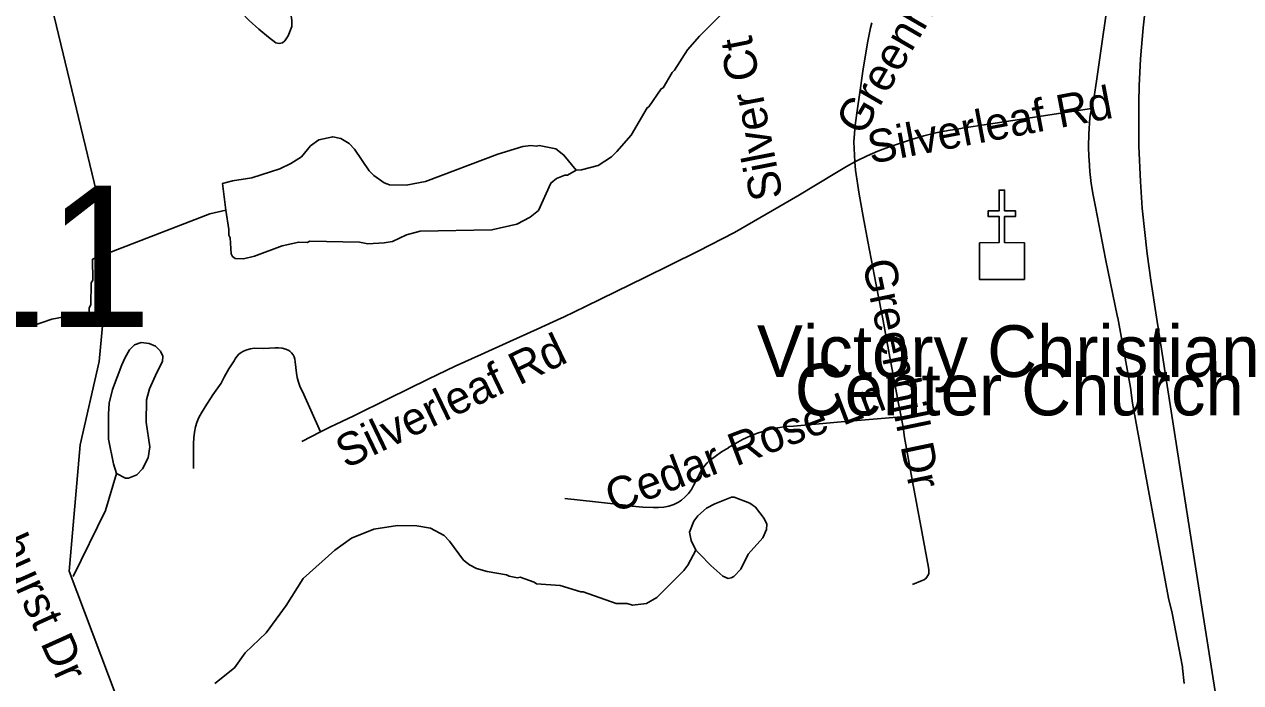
# Model space of a CAD drawing. Extents: x 1383679 to 1536984, y 460658 to 651027.
# Drawn here: x 1435276 to 1438807, y 512005 to 513915 of the extents above; entities that cross this region are included whole.
import ezdxf

# ---------------------------------------------------------------- set-up
doc = ezdxf.new("R2010")
doc.units = 0
for name, color, linetype in [('Exist Cultural Church CELL', 7, 'Continuous'), ('Exist Cultural Church Label', 7, 'Continuous'), ('Exist Hydrographic Creek Single Shore', 7, 'Continuous'), ('Exist Hydrographic Misc Water Feature', 7, 'Continuous'), ('Exist Railroad Mainline', 7, 'Continuous'), ('Exist Road Non-System Type 51', 7, 'Continuous'), ('Exist Road Non-System Type 51 Label', 7, 'Continuous'), ('Exist Road Primary Interstate Structure Ovrhead Sign Number Label', 7, 'Continuous')]:
    doc.layers.add(name, color=color, linetype=linetype)

msp = doc.modelspace()

# ---------------------------------------------------------------- linework, layer by layer
at = {"layer": 'Exist Cultural Church CELL'}
msp.add_lwpolyline([(1438048.9, 513281.7), (1438105.9, 513281.9), (1438105.9, 513358), (1438073.9, 513358), (1438073.9, 513374), (1438105.9, 513374), (1438105.9, 513434.1), (1438121.9, 513434.1), (1438121.9, 513374), (1438153.9, 513374), (1438153.9, 513358), (1438121.9, 513358), (1438121.9, 513281.9), (1438179.5, 513281.7), (1438179.5, 513175.3), (1438048.9, 513175.3)], close=True, dxfattribs=at)
at = {"layer": 'Exist Hydrographic Creek Single Shore'}
msp.add_lwpolyline([(1436493.4, 509139), (1436445.4, 509248.2), (1436458.4, 509458.1), (1436137.4, 510130.8), (1435971.4, 510574), (1435913.4, 510601.5), (1435772.4, 511037.6), (1435792.4, 511227.6), (1435852.4, 511301.8), (1435846.4, 511426.7), (1435659.5, 511647.1), (1435629.4, 511825), (1435564.4, 511908.3), (1435405.4, 512328.4), (1435437.4, 512695.4), (1435492.5, 512937.2), (1435523.4, 513268), (1435362.5, 513937.6), (1435309.4, 514240.7), (1435323.4, 514539.1), (1435285.5, 514707.3), (1435189.5, 514925.8)], dxfattribs=at)
at = {"layer": 'Exist Hydrographic Misc Water Feature'}
for points in [[(1436877.7, 513492.5), (1436893.2, 513492.7), (1436941.5, 513505.6), (1436980.1, 513530.7), (1436996.4, 513546.3), (1437037.5, 513593.4), (1437084.4, 513673.1), (1437089.3, 513676.2), (1437124.9, 513728.5), (1437130.5, 513731.2), (1437156.3, 513775.5), (1437163.6, 513782.5), (1437200.9, 513841.6), (1437235.8, 513880.8), (1437299.1, 513943.4)], [(1435861.1, 513375.9), (1435850.8, 513453), (1435880.4, 513461.5), (1435936.6, 513470.2), (1436017.2, 513496.4), (1436049.5, 513511.7), (1436079.9, 513531), (1436106.6, 513562.3), (1436131, 513579.8), (1436171.2, 513588.9), (1436195, 513584.4), (1436218.7, 513569.8), (1436234.4, 513553.5), (1436277.1, 513490.6), (1436290.8, 513476.3), (1436320.3, 513455.6), (1436336.2, 513449.2), (1436384.2, 513448.2), (1436440.4, 513458.9), (1436650.2, 513538.1), (1436722.6, 513560.5), (1436746.7, 513564), (1436762.7, 513561.6), (1436770.7, 513563.4), (1436818.6, 513554.3), (1436842.2, 513535.8), (1436877.7, 513492.5)], [(1436877.7, 513492.5), (1436853, 513477.6), (1436845, 513477.8), (1436820.7, 513468.4), (1436804.5, 513454.7), (1436768.7, 513375.5), (1436744.3, 513356.1), (1436705.8, 513335), (1436633.4, 513318.6), (1436425.3, 513315.3), (1436385, 513304.2), (1436344.6, 513285.1), (1436320.5, 513281.7), (1436272.5, 513278.7), (1436248.6, 513283.3), (1436104.6, 513286.5), (1436096.5, 513282.7), (1436072.5, 513283.2), (1436024.3, 513272.3), (1435943.7, 513242.1), (1435911.5, 513234.9), (1435887.5, 513235.4), (1435879.6, 513241.6), (1435875.8, 513249.7), (1435872.8, 513295.7), (1435868.9, 513303.8), (1435869.3, 513319.8), (1435861.1, 513375.9)], [(1435473.2, 513233.7), (1435814.3, 513365), (1435861.1, 513375.9)], [(1435473.2, 513233.7), (1435474, 513172.7), (1435469.9, 513164.8), (1435468.4, 513100.9), (1435464.2, 513093), (1435463.9, 513067.9)], [(1435463.9, 513067.9), (1435411.7, 513070.2), (1435355.6, 513059.4), (1435299.1, 513040.7), (1435283.1, 513039.1), (1435267.1, 513041.4), (1435251.3, 513051.8), (1435237.7, 513068.1), (1435222.3, 513096.4), (1435218.6, 513110.5), (1435205, 513128.8), (1435205.2, 513134.8), (1435195.5, 513151), (1435175.9, 513173.4), (1435154.3, 513189.9), (1435126.5, 513200.6), (1435086.8, 513213.4), (1435060.7, 513217.3)], [(1435558.7, 512926.9), (1435568.8, 512948.4), (1435580.7, 512970.4), (1435595.9, 512985.5), (1435614.8, 512991.6), (1435638.2, 512989.2), (1435656.4, 512981.7), (1435671.4, 512966.8), (1435677.5, 512952.7), (1435677.2, 512937.1), (1435660.3, 512904.7)], [(1435543.2, 512611.7), (1435534.5, 512639.6), (1435520, 512711.9), (1435519.6, 512783.9), (1435522.3, 512815.8), (1435531.2, 512855.6), (1435558.7, 512926.9)], [(1435543.2, 512611.7), (1435569.6, 512598.8), (1435577.6, 512598.7), (1435601.8, 512608.1), (1435618.2, 512625.7), (1435634.8, 512657.3), (1435639.6, 512689.2), (1435629.1, 512761.4), (1435630.5, 512825.4), (1435639.3, 512857.2), (1435660.3, 512904.7)], [(1435417, 512313.4), (1435511.5, 512504.2), (1435543.2, 512611.7)], [(1437225.7, 512389.5), (1437237.1, 512377.5), (1437268.5, 512344.8), (1437303.8, 512314), (1437319.7, 512307.6), (1437327.6, 512309.5), (1437335.7, 512313.2), (1437356.3, 512334.8), (1437377.2, 512378.3), (1437420.2, 512425.3), (1437430.8, 512449.1), (1437431.1, 512465), (1437423.4, 512481.2), (1437398.2, 512513.8), (1437382.4, 512526.1), (1437336.8, 512543.2), (1437328.8, 512543.3), (1437280.4, 512524.4), (1437256.1, 512511), (1437231.6, 512489.5), (1437219.3, 512473.8), (1437206.6, 512442.1), (1437212, 512418), (1437225.7, 512389.5)], [(1435828.7, 512003.1), (1435885.7, 512048), (1435916.7, 512091.3), (1435978, 512149.9), (1436035.6, 512228.5), (1436085.3, 512307.4), (1436177.2, 512389.3), (1436225.9, 512424.2), (1436290.5, 512450.7), (1436358.8, 512461.1), (1436414.8, 512459.9), (1436454.6, 512453), (1436494.2, 512432.1), (1436509.8, 512415.8), (1436550.6, 512360.9), (1436568.3, 512346.5), (1436588.1, 512336.1), (1436619.9, 512327.3), (1436675.8, 512318.1), (1436683.7, 512313.9), (1436707.6, 512309.4), (1436715.6, 512311.2), (1436756.4, 512297.1), (1436763.2, 512292.1), (1436831.1, 512286.6), (1436891.2, 512268.6), (1436898.7, 512269.1), (1436994, 512235), (1437026, 512234.3), (1437041.9, 512229.9), (1437082, 512235), (1437112.4, 512252.3), (1437190.2, 512330.5), (1437202.5, 512346.3), (1437225.7, 512389.5)]]:
    msp.add_lwpolyline(points, dxfattribs=at)
at = {"layer": 'Exist Railroad Mainline'}
msp.add_lwpolyline([(1438773.4, 511728.4), (1438664.9, 512414.7), (1438562.6, 513066), (1438546.7, 513173.2), (1438535.6, 513249.8), (1438521.3, 513381.7), (1438516.3, 513459.5), (1438512.1, 513561.9), (1438511.3, 513637.2), (1438511.4, 513689.1), (1438512.5, 513737), (1438516.3, 513815.4), (1438524.8, 513904.7), (1438535.1, 514001.8)], dxfattribs=at)
at = {"layer": 'Exist Road Non-System Type 51'}
msp.add_line((1436135.5, 512732.4), (1436081.5, 512704.8), dxfattribs=at)
for points in [[(1438374.5, 513670.8), (1438381.6, 513705.7), (1438388.6, 513750.2), (1438405.3, 513865), (1438424.5, 513999.8), (1438441.8, 514121.1), (1438450.9, 514185.1)], [(1436018.6, 514091), (1436021.6, 514076.5), (1436036.5, 514014.4), (1436047.9, 513961.4), (1436052.2, 513926.3), (1436052, 513908.8), (1436041.9, 513882.1), (1436031.8, 513867.1), (1436025.6, 513861.7), (1436015.9, 513859.8), (1436006.1, 513861.9), (1435984.6, 513877.7), (1435956, 513901.1), (1435928.6, 513926), (1435904.4, 513951.5), (1435898.9, 513957.9), (1435899.1, 513965.9), (1435905.1, 513974.8), (1435929.8, 514001.4), (1435961.2, 514033.6), (1435993.1, 514065.4), (1436018.6, 514091)], [(1437687.3, 513516.3), (1437684.1, 513574.2), (1437688.5, 513622.7), (1437694.4, 513670.8), (1437700.5, 513710.4), (1437711.5, 513786.3), (1437724.4, 513866.3), (1437732.5, 513904.9), (1437736.1, 513919.5)], [(1437687.3, 513516.3), (1437692.6, 513519.2), (1437722.9, 513533.9), (1437753.8, 513547.2), (1437785.3, 513559.1), (1437817.2, 513569.5), (1437852.1, 513581.4), (1437887.1, 513591.7), (1437922.6, 513600.4), (1437958.3, 513607.6), (1437994.5, 513613.4), (1437999.2, 513614), (1438075, 513625.2), (1438146.2, 513635.8), (1438215.7, 513646.6), (1438297.6, 513659), (1438374.5, 513670.8)], [(1438373.6, 513453.9), (1438369.7, 513488.1), (1438367.2, 513522.5), (1438366.9, 513531), (1438365.5, 513561), (1438366.3, 513596.1), (1438369.4, 513645.4), (1438374.5, 513670.8)], [(1436135.5, 512732.4), (1436162.3, 512746.1), (1436232.6, 512779.4), (1436333.5, 512829.9), (1436448.4, 512885.4), (1436526.7, 512923.2), (1436602, 512957.3), (1436685.3, 512994.8), (1436764.9, 513030.4), (1436833.9, 513062.2), (1436841.6, 513066), (1436904.8, 513097), (1436994.1, 513140.5), (1437077.1, 513180.9), (1437151.4, 513217.3), (1437231.9, 513257.1), (1437337.2, 513310.8), (1437521.7, 513417.7), (1437634, 513485.4), (1437663.1, 513503), (1437687.3, 513516.3)], [(1437821.3, 512776.7), (1437814.2, 512814.7), (1437786.9, 512959.9), (1437767, 513066), (1437754.3, 513133.8), (1437724.9, 513285.5), (1437710.9, 513357.2), (1437699.8, 513422.1), (1437688.7, 513492.2), (1437687.3, 513516.3)], [(1438643, 512002.4), (1438638.6, 512047.5), (1438638.2, 512051.1), (1438608.9, 512206.5), (1438598, 512250.2), (1438539.7, 512563.1), (1438493, 512816.5), (1438488, 512861.3), (1438450.8, 513063.5), (1438450.2, 513066), (1438415.4, 513235.3), (1438386.3, 513385.8), (1438379.1, 513419.9), (1438373.6, 513453.9)], [(1436135.5, 512732.4), (1436082.9, 512849.7), (1436076.5, 512862.6), (1436071.4, 512876.6), (1436067.8, 512891), (1436066.2, 512902.9), (1436062.1, 512935.6), (1436061.3, 512943.5), (1436059.3, 512950.3), (1436056.1, 512956.7), (1436051.7, 512962.4), (1436046.3, 512967.2), (1436043.9, 512968.8), (1436034.4, 512972.7), (1436024.2, 512975.3), (1436013.7, 512976.5), (1436003.9, 512976.3), (1435970.6, 512975.1), (1435943.1, 512975.3), (1435932.3, 512973.8), (1435921.9, 512970.8), (1435911.8, 512966.5), (1435905.6, 512962.9), (1435898.7, 512957.8), (1435892.9, 512951.8), (1435888.1, 512944.8), (1435885.3, 512939.2), (1435869.8, 512915.8), (1435856, 512891.9), (1435847, 512874.5), (1435823.1, 512840.2), (1435800.9, 512805.4), (1435798.2, 512801), (1435789.5, 512787.9), (1435782.4, 512774.5), (1435776.7, 512760.4), (1435772.9, 512747.8), (1435769.4, 512731.9), (1435767.4, 512715.7), (1435766.9, 512699.4), (1435767.1, 512693.1), (1435767.2, 512626.5)], [(1437821.3, 512776.7), (1437647, 512761.8), (1437508.6, 512749.5), (1437485.6, 512747.9), (1437463.4, 512744.8), (1437441.4, 512740.2), (1437419.8, 512734.1), (1437404, 512728.6), (1437382.1, 512720.3), (1437360.9, 512710.6), (1437340.5, 512699.5), (1437320.7, 512687), (1437320.1, 512686.6), (1437300, 512674.6), (1437281.3, 512661.7), (1437267.4, 512650.7), (1437258.6, 512643.1), (1437251.1, 512634.8), (1437244.6, 512625.5), (1437242.2, 512621.2), (1437219.1, 512577.4), (1437212.7, 512565.6), (1437204.5, 512554.1), (1437194.9, 512543.8), (1437184.2, 512534.8), (1437175, 512528.7), (1437161.3, 512522.2), (1437147.1, 512517.5), (1437132.4, 512514.4), (1437117.4, 512513), (1437102.7, 512513.3), (1437101.6, 512513.4), (1437071.4, 512514.6), (1437040.9, 512517.5), (1437029.8, 512518.9), (1436934.1, 512529.3), (1436845.3, 512539.1)], [(1437854.6, 512290.2), (1437882.9, 512301.3), (1437887.4, 512303.4), (1437892.3, 512306.8), (1437896.3, 512310.9), (1437899.4, 512315.8), (1437901.5, 512321.2), (1437901.9, 512327.6), (1437901.6, 512332.6), (1437900.7, 512339.7), (1437882.1, 512443.4), (1437854.5, 512588.9), (1437831.7, 512716.4), (1437827, 512746.4), (1437821.3, 512776.7)]]:
    msp.add_lwpolyline(points, dxfattribs=at)

# ---------------------------------------------------------------- texts
at = {"layer": 'Exist Cultural Church Label'}
for s, p in [('Victory Christian ', (1437402.6, 512892.1)), ('Center Church', (1437512.5, 512780.6))]:
    msp.add_text(s, height=150, rotation=0, dxfattribs=at).set_placement(p)
at = {"layer": 'Exist Road Non-System Type 51 Label'}
for s, rotation, p in [('Greenhill Dr', 59.8981, (1437709.4, 513588.2)), ('Silver Ct', 101.0816, (1437478.8, 513414.2)), ('Silverleaf Rd', 10.7525, (1437733.8, 513510.3)), ('Greenhill Dr', 281.7172, (1437708.9, 513224.5)), ('Silverleaf Rd', 25.6736, (1436209.3, 512624.9)), ('Cedar Rose Ln', 20.8431, (1436985.2, 512496.2)), ('Farmhurst Dr', 294.2276, (1435069.2, 512680.4))]:
    msp.add_text(s, height=95, rotation=rotation, dxfattribs=at).set_placement(p)
at = {"layer": 'Exist Road Primary Interstate Structure Ovrhead Sign Number Label'}
msp.add_text('S611', height=410.1, dxfattribs=at).set_placement((1434364.7, 513036.8))

doc.saveas('drawing.dxf')
